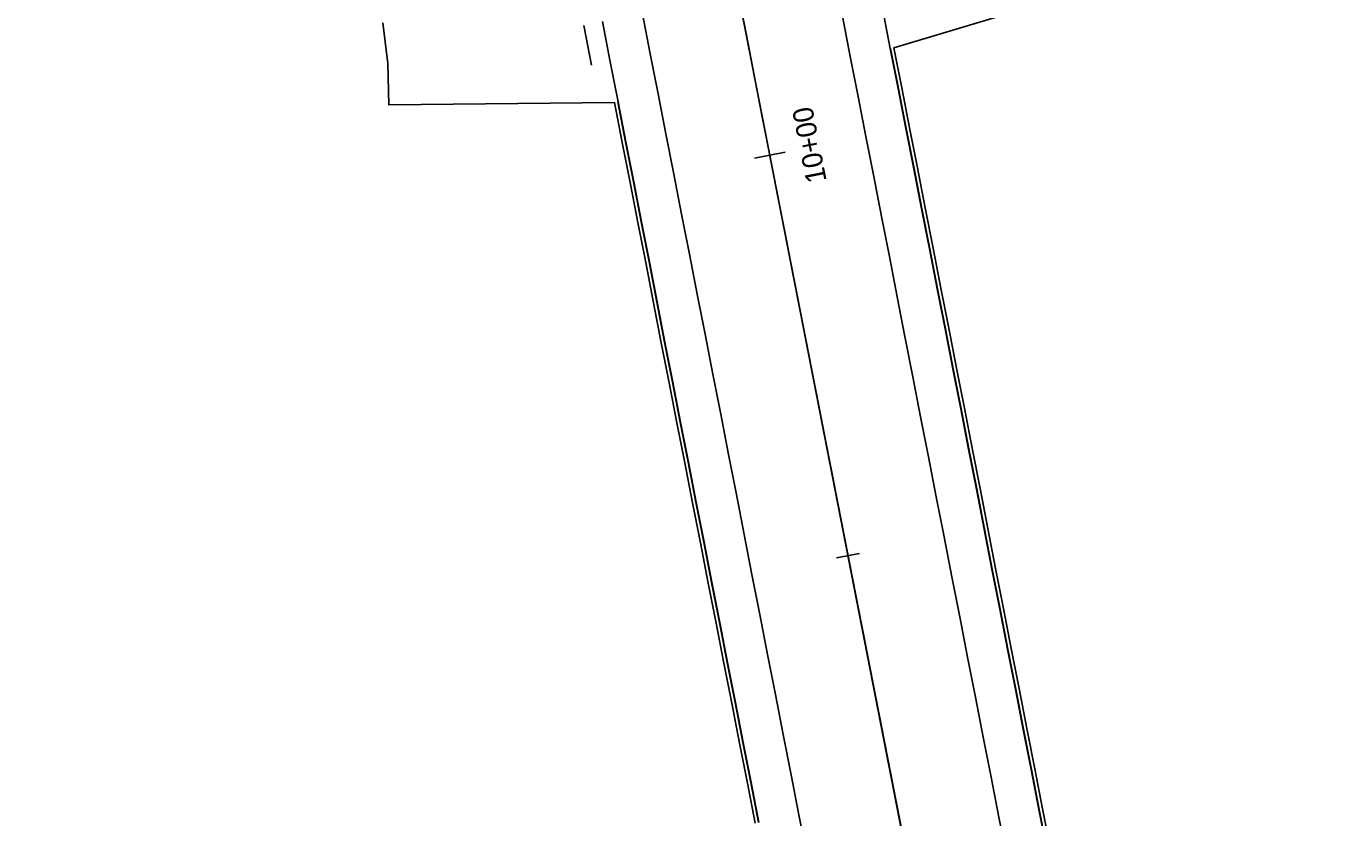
# Model space of a CAD drawing. Extents: x 1150550 to 1151113, y 1141187 to 1143500.
# Drawn here: x 1150711.8 to 1150873.1, y 1141904 to 1142001 of the extents above; entities that cross this region are included whole.
import ezdxf

# ---------------------------------------------------------------- set-up
doc = ezdxf.new("R2010")
doc.units = 0
for name, color, linetype in [('AC_P', 7, 'Continuous'), ('ACSR_P_T', 7, 'Continuous'), ('ACSRT_P', 7, 'Continuous'), ('Default', 7, 'Continuous'), ('LELB_P', 7, 'Continuous'), ('LFILL_P', 7, 'Continuous'), ('PE_P', 7, 'Continuous'), ('PET_P', 7, 'Continuous'), ('RC_P', 7, 'Continuous'), ('XSCTOP1_P', 7, 'Continuous')]:
    doc.layers.add(name, color=color, linetype=linetype)

msp = doc.modelspace()

# ---------------------------------------------------------------- linework, layer by layer
at = {"layer": 'AC_P'}
msp.add_line((1150819.56, 1141899.84), (1150776.47, 1142120.43), dxfattribs=at)
msp.add_lwpolyline([(1150819.18, 1141901.8), (1150818.22, 1141906.71), (1150817.26, 1141911.61), (1150816.3, 1141916.52), (1150815.35, 1141921.43), (1150814.39, 1141926.34), (1150813.43, 1141931.24), (1150812.47, 1141936.15), (1150811.51, 1141941.06), (1150810.55, 1141945.96), (1150809.59, 1141950.87), (1150808.64, 1141955.78), (1150807.68, 1141960.69), (1150806.72, 1141965.59), (1150805.76, 1141970.5), (1150804.8, 1141975.41), (1150803.84, 1141980.32), (1150802.88, 1141985.22), (1150801.92, 1141990.13), (1150800.97, 1141995.04), (1150800.01, 1141999.94), (1150799.05, 1142004.85)], dxfattribs=at)
at = {"layer": 'ACSRT_P'}
for points in [[(1150801, 1141984.85), (1150804.77, 1141985.59)], [(1150811.06, 1141935.87), (1150813.88, 1141936.43)]]:
    msp.add_lwpolyline(points, dxfattribs=at)
at = {"layer": 'Default'}
msp.add_line((1150956.27, 1141200.06), (1150657.48, 1142729.55), dxfattribs=at)
for points in [[(1150836.82, 1141900.15), (1150835.87, 1141905.06), (1150834.91, 1141909.97), (1150833.95, 1141914.87), (1150832.99, 1141919.78), (1150832.03, 1141924.69), (1150831.07, 1141929.6), (1150830.11, 1141934.5), (1150829.15, 1141939.41), (1150828.2, 1141944.32), (1150827.24, 1141949.22), (1150826.28, 1141954.13), (1150825.32, 1141959.04), (1150824.36, 1141963.95), (1150823.4, 1141968.85), (1150822.44, 1141973.76), (1150821.49, 1141978.67), (1150820.53, 1141983.57), (1150819.57, 1141988.48), (1150818.61, 1141993.39), (1150817.65, 1141998.3)], [(1150836.82, 1141900.15), (1150835.87, 1141905.06), (1150834.91, 1141909.97), (1150833.95, 1141914.87), (1150832.99, 1141919.78), (1150832.03, 1141924.69), (1150831.07, 1141929.6), (1150830.11, 1141934.5), (1150829.15, 1141939.41), (1150828.2, 1141944.32), (1150827.24, 1141949.22), (1150826.28, 1141954.13), (1150825.32, 1141959.04), (1150824.36, 1141963.95), (1150823.4, 1141968.85), (1150822.44, 1141973.76), (1150821.49, 1141978.67), (1150820.53, 1141983.57), (1150819.57, 1141988.48), (1150818.61, 1141993.39), (1150817.65, 1141998.3)], [(1150801.54, 1141903.45), (1150800.58, 1141908.35), (1150799.62, 1141913.26), (1150798.66, 1141918.17), (1150797.7, 1141923.08), (1150796.74, 1141927.98), (1150795.79, 1141932.89), (1150794.83, 1141937.8), (1150793.87, 1141942.71), (1150792.91, 1141947.61), (1150791.95, 1141952.52), (1150790.99, 1141957.43), (1150790.03, 1141962.33), (1150789.07, 1141967.24), (1150788.12, 1141972.15), (1150787.16, 1141977.06), (1150786.2, 1141981.96), (1150785.24, 1141986.87), (1150784.28, 1141991.78)], [(1150801.54, 1141903.45), (1150800.58, 1141908.35), (1150799.62, 1141913.26), (1150798.66, 1141918.17), (1150797.7, 1141923.08), (1150796.74, 1141927.98), (1150795.79, 1141932.89), (1150794.83, 1141937.8), (1150793.87, 1141942.71), (1150792.91, 1141947.61), (1150791.95, 1141952.52), (1150790.99, 1141957.43), (1150790.03, 1141962.33), (1150789.07, 1141967.24), (1150788.12, 1141972.15), (1150787.16, 1141977.06), (1150786.2, 1141981.96), (1150785.24, 1141986.87), (1150784.28, 1141991.78)]]:
    msp.add_lwpolyline(points, dxfattribs=at)
at = {"layer": 'LELB_P'}
for points in [[(1150866.65, 1142012.96), (1150818.1, 1141998.38), (1150819.06, 1141993.48), (1150820.02, 1141988.57), (1150820.98, 1141983.66), (1150821.94, 1141978.76), (1150822.89, 1141973.85), (1150823.85, 1141968.94), (1150824.81, 1141964.03), (1150825.77, 1141959.13), (1150826.73, 1141954.22), (1150827.69, 1141949.31), (1150828.65, 1141944.4), (1150829.6, 1141939.5), (1150830.56, 1141934.59), (1150831.52, 1141929.68), (1150832.48, 1141924.78), (1150833.44, 1141919.87), (1150834.4, 1141914.96), (1150835.36, 1141910.05), (1150836.31, 1141905.15), (1150837.27, 1141900.24)], [(1150801.09, 1141903.36), (1150800.13, 1141908.27), (1150799.17, 1141913.17), (1150798.21, 1141918.08), (1150797.25, 1141922.99), (1150796.29, 1141927.9), (1150795.34, 1141932.8), (1150794.38, 1141937.71), (1150793.42, 1141942.62), (1150792.46, 1141947.52), (1150791.5, 1141952.43), (1150790.54, 1141957.34), (1150789.58, 1141962.25), (1150788.62, 1141967.15), (1150787.67, 1141972.06), (1150786.71, 1141976.97), (1150785.75, 1141981.88), (1150784.79, 1141986.78), (1150783.83, 1141991.69), (1150756.19, 1141991.38), (1150756.08, 1141996.46), (1150755.47, 1142001.43)], [(1150781.03, 1141996.24), (1150780.07, 1142001.14)], [(1150836.86, 1141900.16), (1150835.91, 1141905.07), (1150834.95, 1141909.97), (1150833.99, 1141914.88), (1150833.03, 1141919.79), (1150832.07, 1141924.7), (1150831.11, 1141929.6), (1150830.15, 1141934.51), (1150829.2, 1141939.42), (1150828.24, 1141944.33), (1150827.28, 1141949.23), (1150826.32, 1141954.14), (1150825.36, 1141959.05), (1150824.4, 1141963.95), (1150823.44, 1141968.86), (1150822.48, 1141973.77), (1150821.53, 1141978.68), (1150820.57, 1141983.58), (1150819.61, 1141988.49), (1150818.65, 1141993.4), (1150817.69, 1141998.3)], [(1150801.5, 1141903.44), (1150800.54, 1141908.35), (1150799.58, 1141913.25), (1150798.62, 1141918.16), (1150797.66, 1141923.07), (1150796.7, 1141927.98), (1150795.74, 1141932.88), (1150794.79, 1141937.79), (1150793.83, 1141942.7), (1150792.87, 1141947.6), (1150791.91, 1141952.51), (1150790.95, 1141957.42), (1150789.99, 1141962.33), (1150789.03, 1141967.23), (1150788.08, 1141972.14), (1150787.12, 1141977.05), (1150786.16, 1141981.96), (1150785.2, 1141986.86), (1150784.24, 1141991.77)]]:
    msp.add_lwpolyline(points, dxfattribs=at)
at = {"layer": 'LFILL_P'}
msp.add_lwpolyline([(1150756.19, 1141991.38), (1150756.08, 1141996.46), (1150755.47, 1142001.43)], dxfattribs=at)
at = {"layer": 'PE_P'}
for points in [[(1150836.82, 1141900.15), (1150835.87, 1141905.06), (1150834.91, 1141909.97), (1150833.95, 1141914.87), (1150832.99, 1141919.78), (1150832.03, 1141924.69), (1150831.07, 1141929.6), (1150830.11, 1141934.5), (1150829.15, 1141939.41), (1150828.2, 1141944.32), (1150827.24, 1141949.22), (1150826.28, 1141954.13), (1150825.32, 1141959.04), (1150824.36, 1141963.95), (1150823.4, 1141968.85), (1150822.44, 1141973.76), (1150821.49, 1141978.67), (1150820.53, 1141983.57), (1150819.57, 1141988.48), (1150818.61, 1141993.39), (1150817.65, 1141998.3), (1150816.69, 1142003.2)], [(1150801.54, 1141903.45), (1150800.58, 1141908.35), (1150799.62, 1141913.26), (1150798.66, 1141918.17), (1150797.7, 1141923.08), (1150796.74, 1141927.98), (1150795.79, 1141932.89), (1150794.83, 1141937.8), (1150793.87, 1141942.71), (1150792.91, 1141947.61), (1150791.95, 1141952.52), (1150790.99, 1141957.43), (1150790.03, 1141962.33), (1150789.07, 1141967.24), (1150788.12, 1141972.15), (1150787.16, 1141977.06), (1150786.2, 1141981.96), (1150785.24, 1141986.87), (1150784.28, 1141991.78), (1150783.32, 1141996.68), (1150782.36, 1142001.59)], [(1150801.54, 1141903.45), (1150800.58, 1141908.35), (1150799.62, 1141913.26), (1150798.66, 1141918.17), (1150797.7, 1141923.08), (1150796.74, 1141927.98), (1150795.79, 1141932.89), (1150794.83, 1141937.8), (1150793.87, 1141942.71), (1150792.91, 1141947.61), (1150791.95, 1141952.52), (1150790.99, 1141957.43), (1150790.03, 1141962.33), (1150789.07, 1141967.24), (1150788.12, 1141972.15), (1150787.16, 1141977.06), (1150786.2, 1141981.96), (1150785.24, 1141986.87), (1150784.28, 1141991.78)]]:
    msp.add_lwpolyline(points, dxfattribs=at)
at = {"layer": 'PET_P'}
for points in [[(1150807.4, 1141899.5), (1150806.44, 1141904.41), (1150805.49, 1141909.31), (1150804.53, 1141914.22), (1150803.57, 1141919.13), (1150802.61, 1141924.04), (1150801.65, 1141928.94), (1150800.69, 1141933.85), (1150799.73, 1141938.76), (1150798.78, 1141943.66), (1150797.82, 1141948.57), (1150796.86, 1141953.48), (1150795.9, 1141958.39), (1150794.94, 1141963.29), (1150793.98, 1141968.2), (1150793.02, 1141973.11), (1150792.06, 1141978.01), (1150791.11, 1141982.92), (1150790.15, 1141987.83), (1150789.19, 1141992.74), (1150788.23, 1141997.64), (1150787.27, 1142002.55)], [(1150831.92, 1141899.19), (1150830.96, 1141904.1), (1150830, 1141909.01), (1150829.04, 1141913.91), (1150828.08, 1141918.82), (1150827.12, 1141923.73), (1150826.16, 1141928.64), (1150825.21, 1141933.54), (1150824.25, 1141938.45), (1150823.29, 1141943.36), (1150822.33, 1141948.27), (1150821.37, 1141953.17), (1150820.41, 1141958.08), (1150819.45, 1141962.99), (1150818.5, 1141967.89), (1150817.54, 1141972.8), (1150816.58, 1141977.71), (1150815.62, 1141982.62), (1150814.66, 1141987.52), (1150813.7, 1141992.43), (1150812.74, 1141997.34), (1150811.78, 1142002.25)]]:
    msp.add_lwpolyline(points, dxfattribs=at)
at = {"layer": 'RC_P'}
for points in [[(1150837.27, 1141900.24), (1150836.31, 1141905.15), (1150835.36, 1141910.05), (1150834.4, 1141914.96), (1150833.44, 1141919.87), (1150832.48, 1141924.78), (1150831.52, 1141929.68), (1150830.56, 1141934.59), (1150829.6, 1141939.5), (1150828.65, 1141944.4), (1150827.69, 1141949.31), (1150826.73, 1141954.22), (1150825.77, 1141959.13), (1150824.81, 1141964.03), (1150823.85, 1141968.94), (1150822.89, 1141973.85), (1150821.94, 1141978.76), (1150820.98, 1141983.66), (1150820.02, 1141988.57), (1150819.06, 1141993.48), (1150818.1, 1141998.38)], [(1150837.27, 1141900.24), (1150836.31, 1141905.15), (1150835.36, 1141910.05), (1150834.4, 1141914.96), (1150833.44, 1141919.87), (1150832.48, 1141924.78), (1150831.52, 1141929.68), (1150830.56, 1141934.59), (1150829.6, 1141939.5), (1150828.65, 1141944.4), (1150827.69, 1141949.31), (1150826.73, 1141954.22), (1150825.77, 1141959.13), (1150824.81, 1141964.03), (1150823.85, 1141968.94), (1150822.89, 1141973.85), (1150821.94, 1141978.76), (1150820.98, 1141983.66), (1150820.02, 1141988.57), (1150819.06, 1141993.48), (1150818.1, 1141998.38)], [(1150801.09, 1141903.36), (1150800.13, 1141908.27), (1150799.17, 1141913.17), (1150798.21, 1141918.08), (1150797.25, 1141922.99), (1150796.29, 1141927.9), (1150795.34, 1141932.8), (1150794.38, 1141937.71), (1150793.42, 1141942.62), (1150792.46, 1141947.52), (1150791.5, 1141952.43), (1150790.54, 1141957.34), (1150789.58, 1141962.25), (1150788.62, 1141967.15), (1150787.67, 1141972.06), (1150786.71, 1141976.97), (1150785.75, 1141981.88), (1150784.79, 1141986.78), (1150783.83, 1141991.69)], [(1150801.09, 1141903.36), (1150800.13, 1141908.27), (1150799.17, 1141913.17), (1150798.21, 1141918.08), (1150797.25, 1141922.99), (1150796.29, 1141927.9), (1150795.34, 1141932.8), (1150794.38, 1141937.71), (1150793.42, 1141942.62), (1150792.46, 1141947.52), (1150791.5, 1141952.43), (1150790.54, 1141957.34), (1150789.58, 1141962.25), (1150788.62, 1141967.15), (1150787.67, 1141972.06), (1150786.71, 1141976.97), (1150785.75, 1141981.88), (1150784.79, 1141986.78), (1150783.83, 1141991.69)]]:
    msp.add_lwpolyline(points, dxfattribs=at)
at = {"layer": 'XSCTOP1_P'}
for points in [[(1150819.18, 1141901.8), (1150818.22, 1141906.71), (1150817.26, 1141911.61), (1150816.3, 1141916.52), (1150815.35, 1141921.43), (1150814.39, 1141926.34), (1150813.43, 1141931.24), (1150812.47, 1141936.15), (1150811.51, 1141941.06), (1150810.55, 1141945.96), (1150809.59, 1141950.87), (1150808.64, 1141955.78), (1150807.68, 1141960.69), (1150806.72, 1141965.59), (1150805.76, 1141970.5), (1150804.8, 1141975.41), (1150803.84, 1141980.32), (1150802.88, 1141985.22), (1150801.92, 1141990.13), (1150800.97, 1141995.04), (1150800.01, 1141999.94), (1150799.05, 1142004.85)], [(1150836.82, 1141900.15), (1150835.87, 1141905.06), (1150834.91, 1141909.97), (1150833.95, 1141914.87), (1150832.99, 1141919.78), (1150832.03, 1141924.69), (1150831.07, 1141929.6), (1150830.11, 1141934.5), (1150829.15, 1141939.41), (1150828.2, 1141944.32), (1150827.24, 1141949.22), (1150826.28, 1141954.13), (1150825.32, 1141959.04), (1150824.36, 1141963.95), (1150823.4, 1141968.85), (1150822.44, 1141973.76), (1150821.49, 1141978.67), (1150820.53, 1141983.57), (1150819.57, 1141988.48), (1150818.61, 1141993.39), (1150817.65, 1141998.3), (1150816.69, 1142003.2)], [(1150801.54, 1141903.45), (1150800.58, 1141908.35), (1150799.62, 1141913.26), (1150798.66, 1141918.17), (1150797.7, 1141923.08), (1150796.74, 1141927.98), (1150795.79, 1141932.89), (1150794.83, 1141937.8), (1150793.87, 1141942.71), (1150792.91, 1141947.61), (1150791.95, 1141952.52), (1150790.99, 1141957.43), (1150790.03, 1141962.33), (1150789.07, 1141967.24), (1150788.12, 1141972.15), (1150787.16, 1141977.06), (1150786.2, 1141981.96), (1150785.24, 1141986.87), (1150784.28, 1141991.78), (1150783.32, 1141996.68), (1150782.36, 1142001.59)], [(1150807.4, 1141899.5), (1150806.44, 1141904.41), (1150805.49, 1141909.31), (1150804.53, 1141914.22), (1150803.57, 1141919.13), (1150802.61, 1141924.04), (1150801.65, 1141928.94), (1150800.69, 1141933.85), (1150799.73, 1141938.76), (1150798.78, 1141943.66), (1150797.82, 1141948.57), (1150796.86, 1141953.48), (1150795.9, 1141958.39), (1150794.94, 1141963.29), (1150793.98, 1141968.2), (1150793.02, 1141973.11), (1150792.06, 1141978.01), (1150791.11, 1141982.92), (1150790.15, 1141987.83), (1150789.19, 1141992.74), (1150788.23, 1141997.64), (1150787.27, 1142002.55)], [(1150831.92, 1141899.19), (1150830.96, 1141904.1), (1150830, 1141909.01), (1150829.04, 1141913.91), (1150828.08, 1141918.82), (1150827.12, 1141923.73), (1150826.16, 1141928.64), (1150825.21, 1141933.54), (1150824.25, 1141938.45), (1150823.29, 1141943.36), (1150822.33, 1141948.27), (1150821.37, 1141953.17), (1150820.41, 1141958.08), (1150819.45, 1141962.99), (1150818.5, 1141967.89), (1150817.54, 1141972.8), (1150816.58, 1141977.71), (1150815.62, 1141982.62), (1150814.66, 1141987.52), (1150813.7, 1141992.43), (1150812.74, 1141997.34), (1150811.78, 1142002.25)]]:
    msp.add_lwpolyline(points, dxfattribs=at)

# ---------------------------------------------------------------- texts
at = {"layer": 'ACSR_P_T'}
msp.add_text('10+00', height=2.501, rotation=101.0539, dxfattribs=at).set_placement((1150809.86, 1141982.1))

doc.saveas('drawing.dxf')
